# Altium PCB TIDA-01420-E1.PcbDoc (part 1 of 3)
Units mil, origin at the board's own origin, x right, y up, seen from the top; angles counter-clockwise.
Board outline 6575 x 7007.88 mil, 4 copper layers (Top Layer, GND, PWR, Bottom Layer), stack 79.834 mil thick; 326 components, 128 nets, 736 pads, 186 vias.
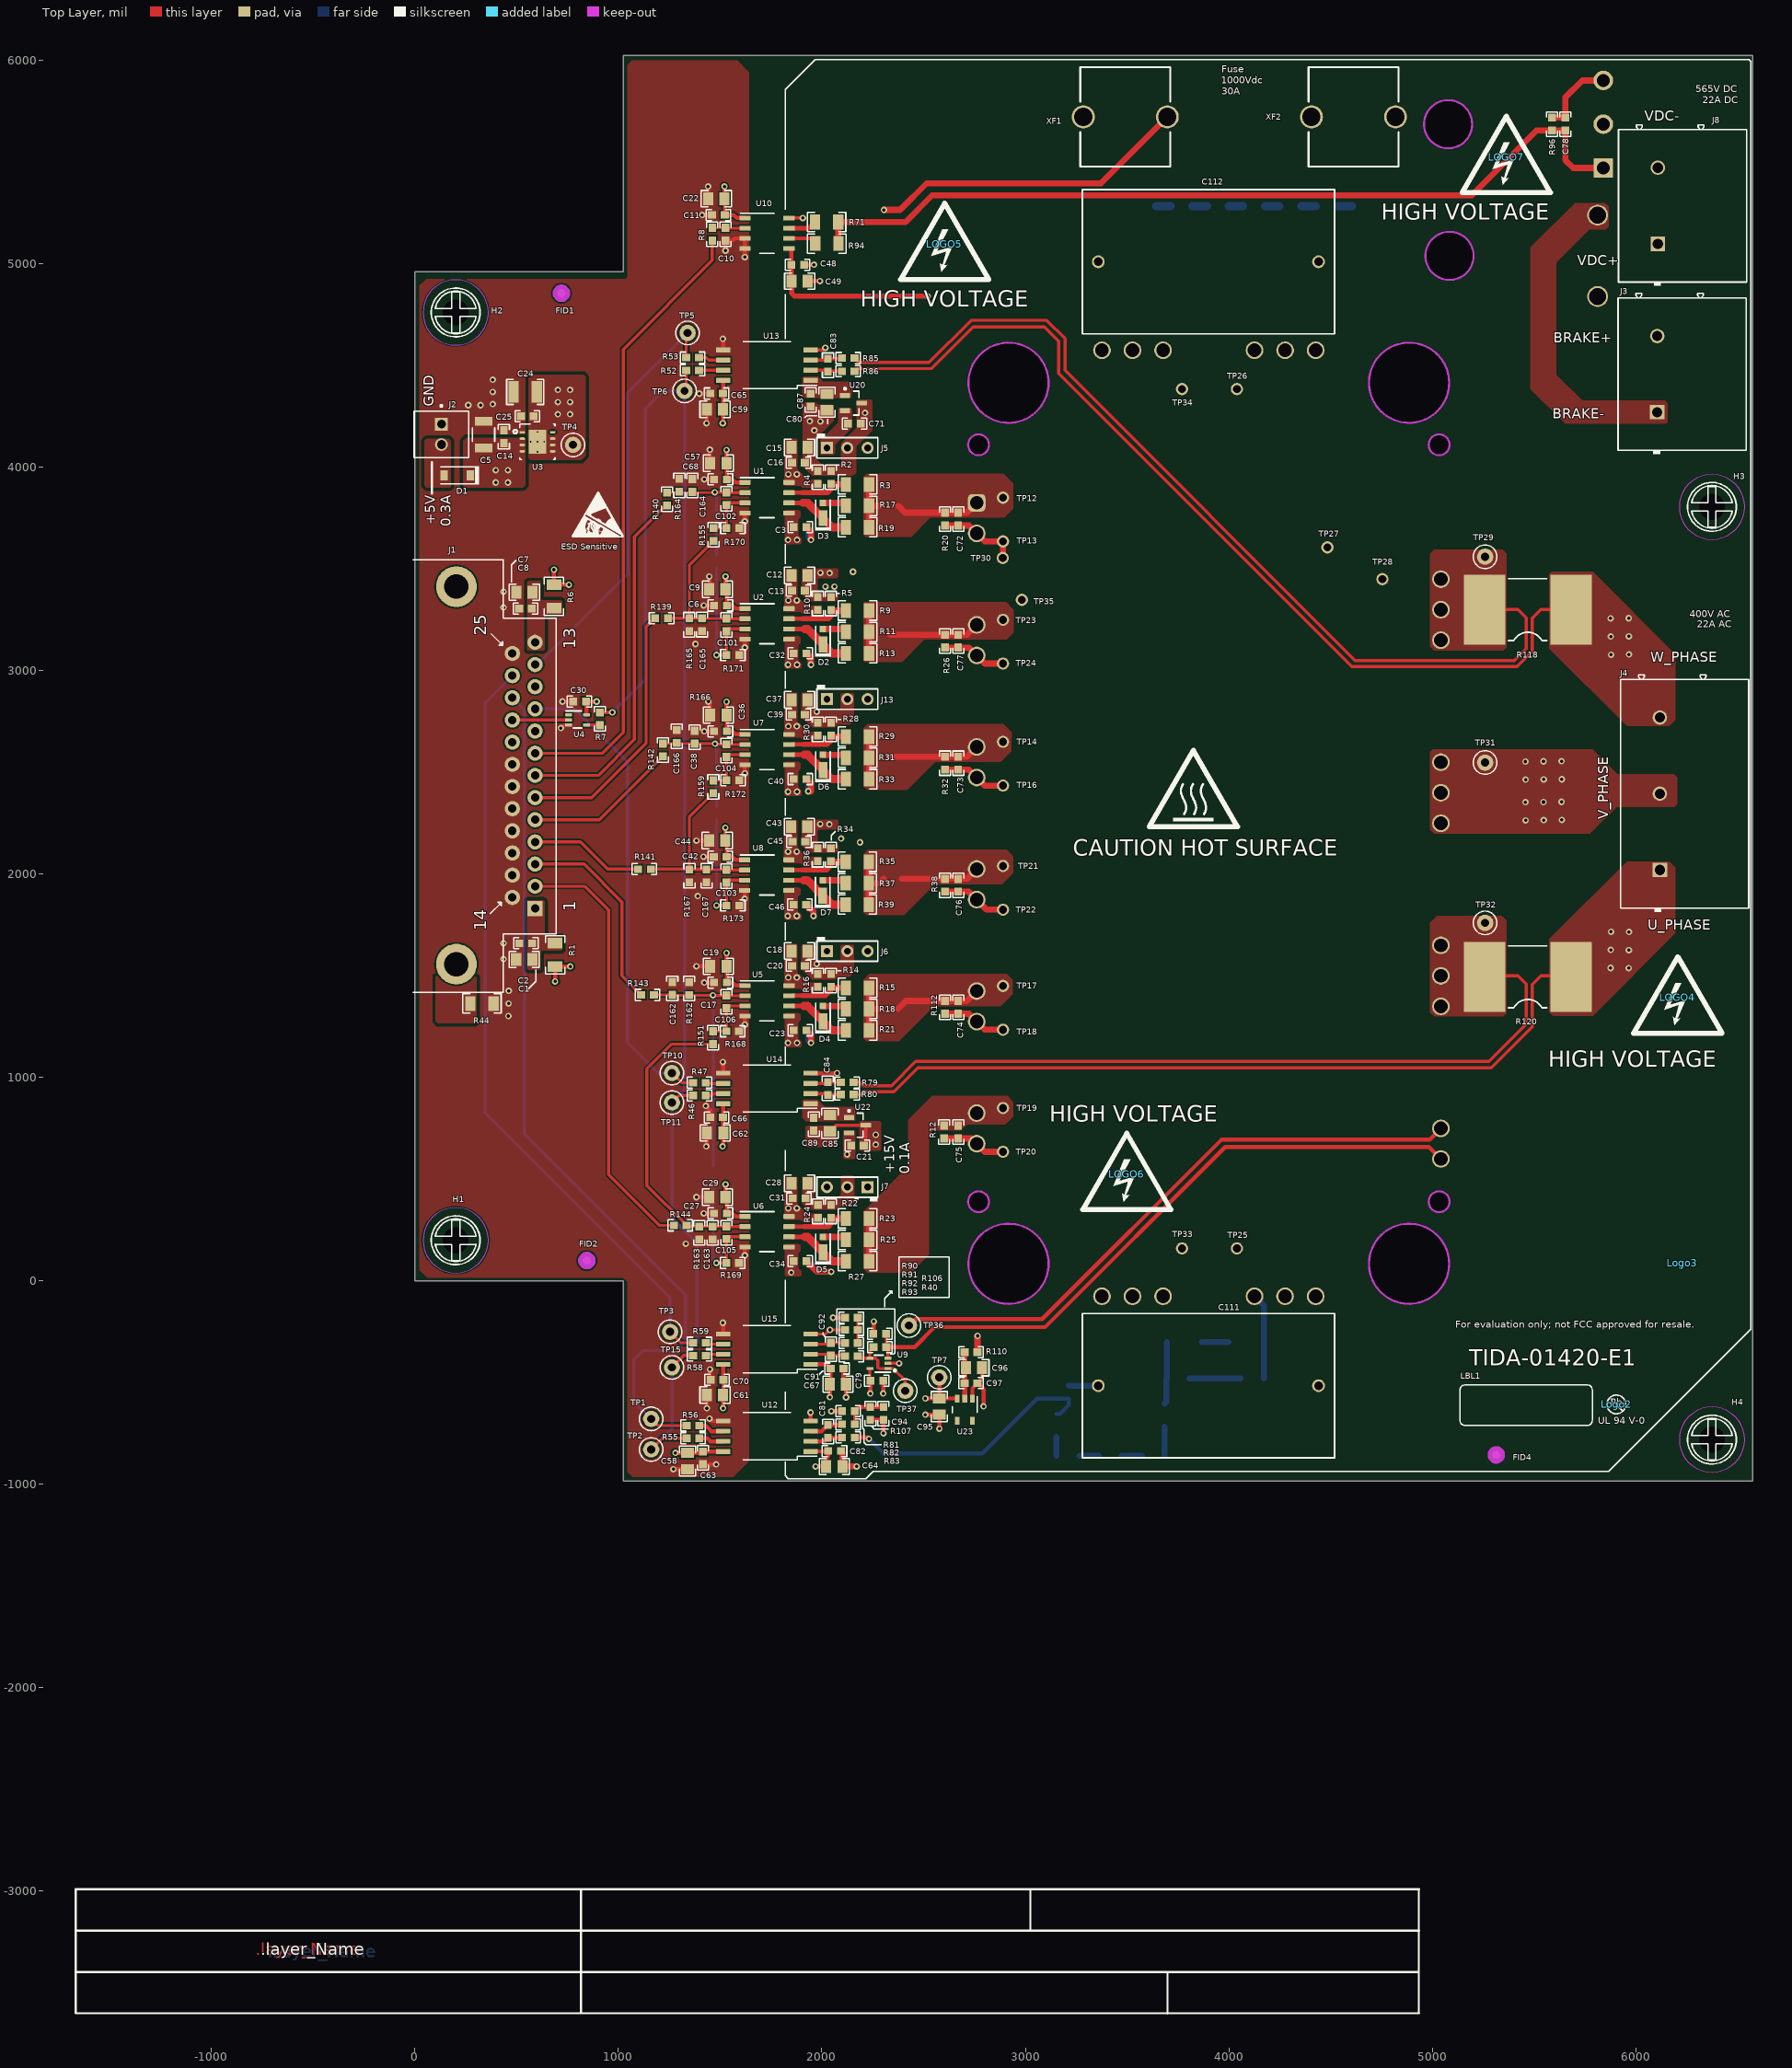
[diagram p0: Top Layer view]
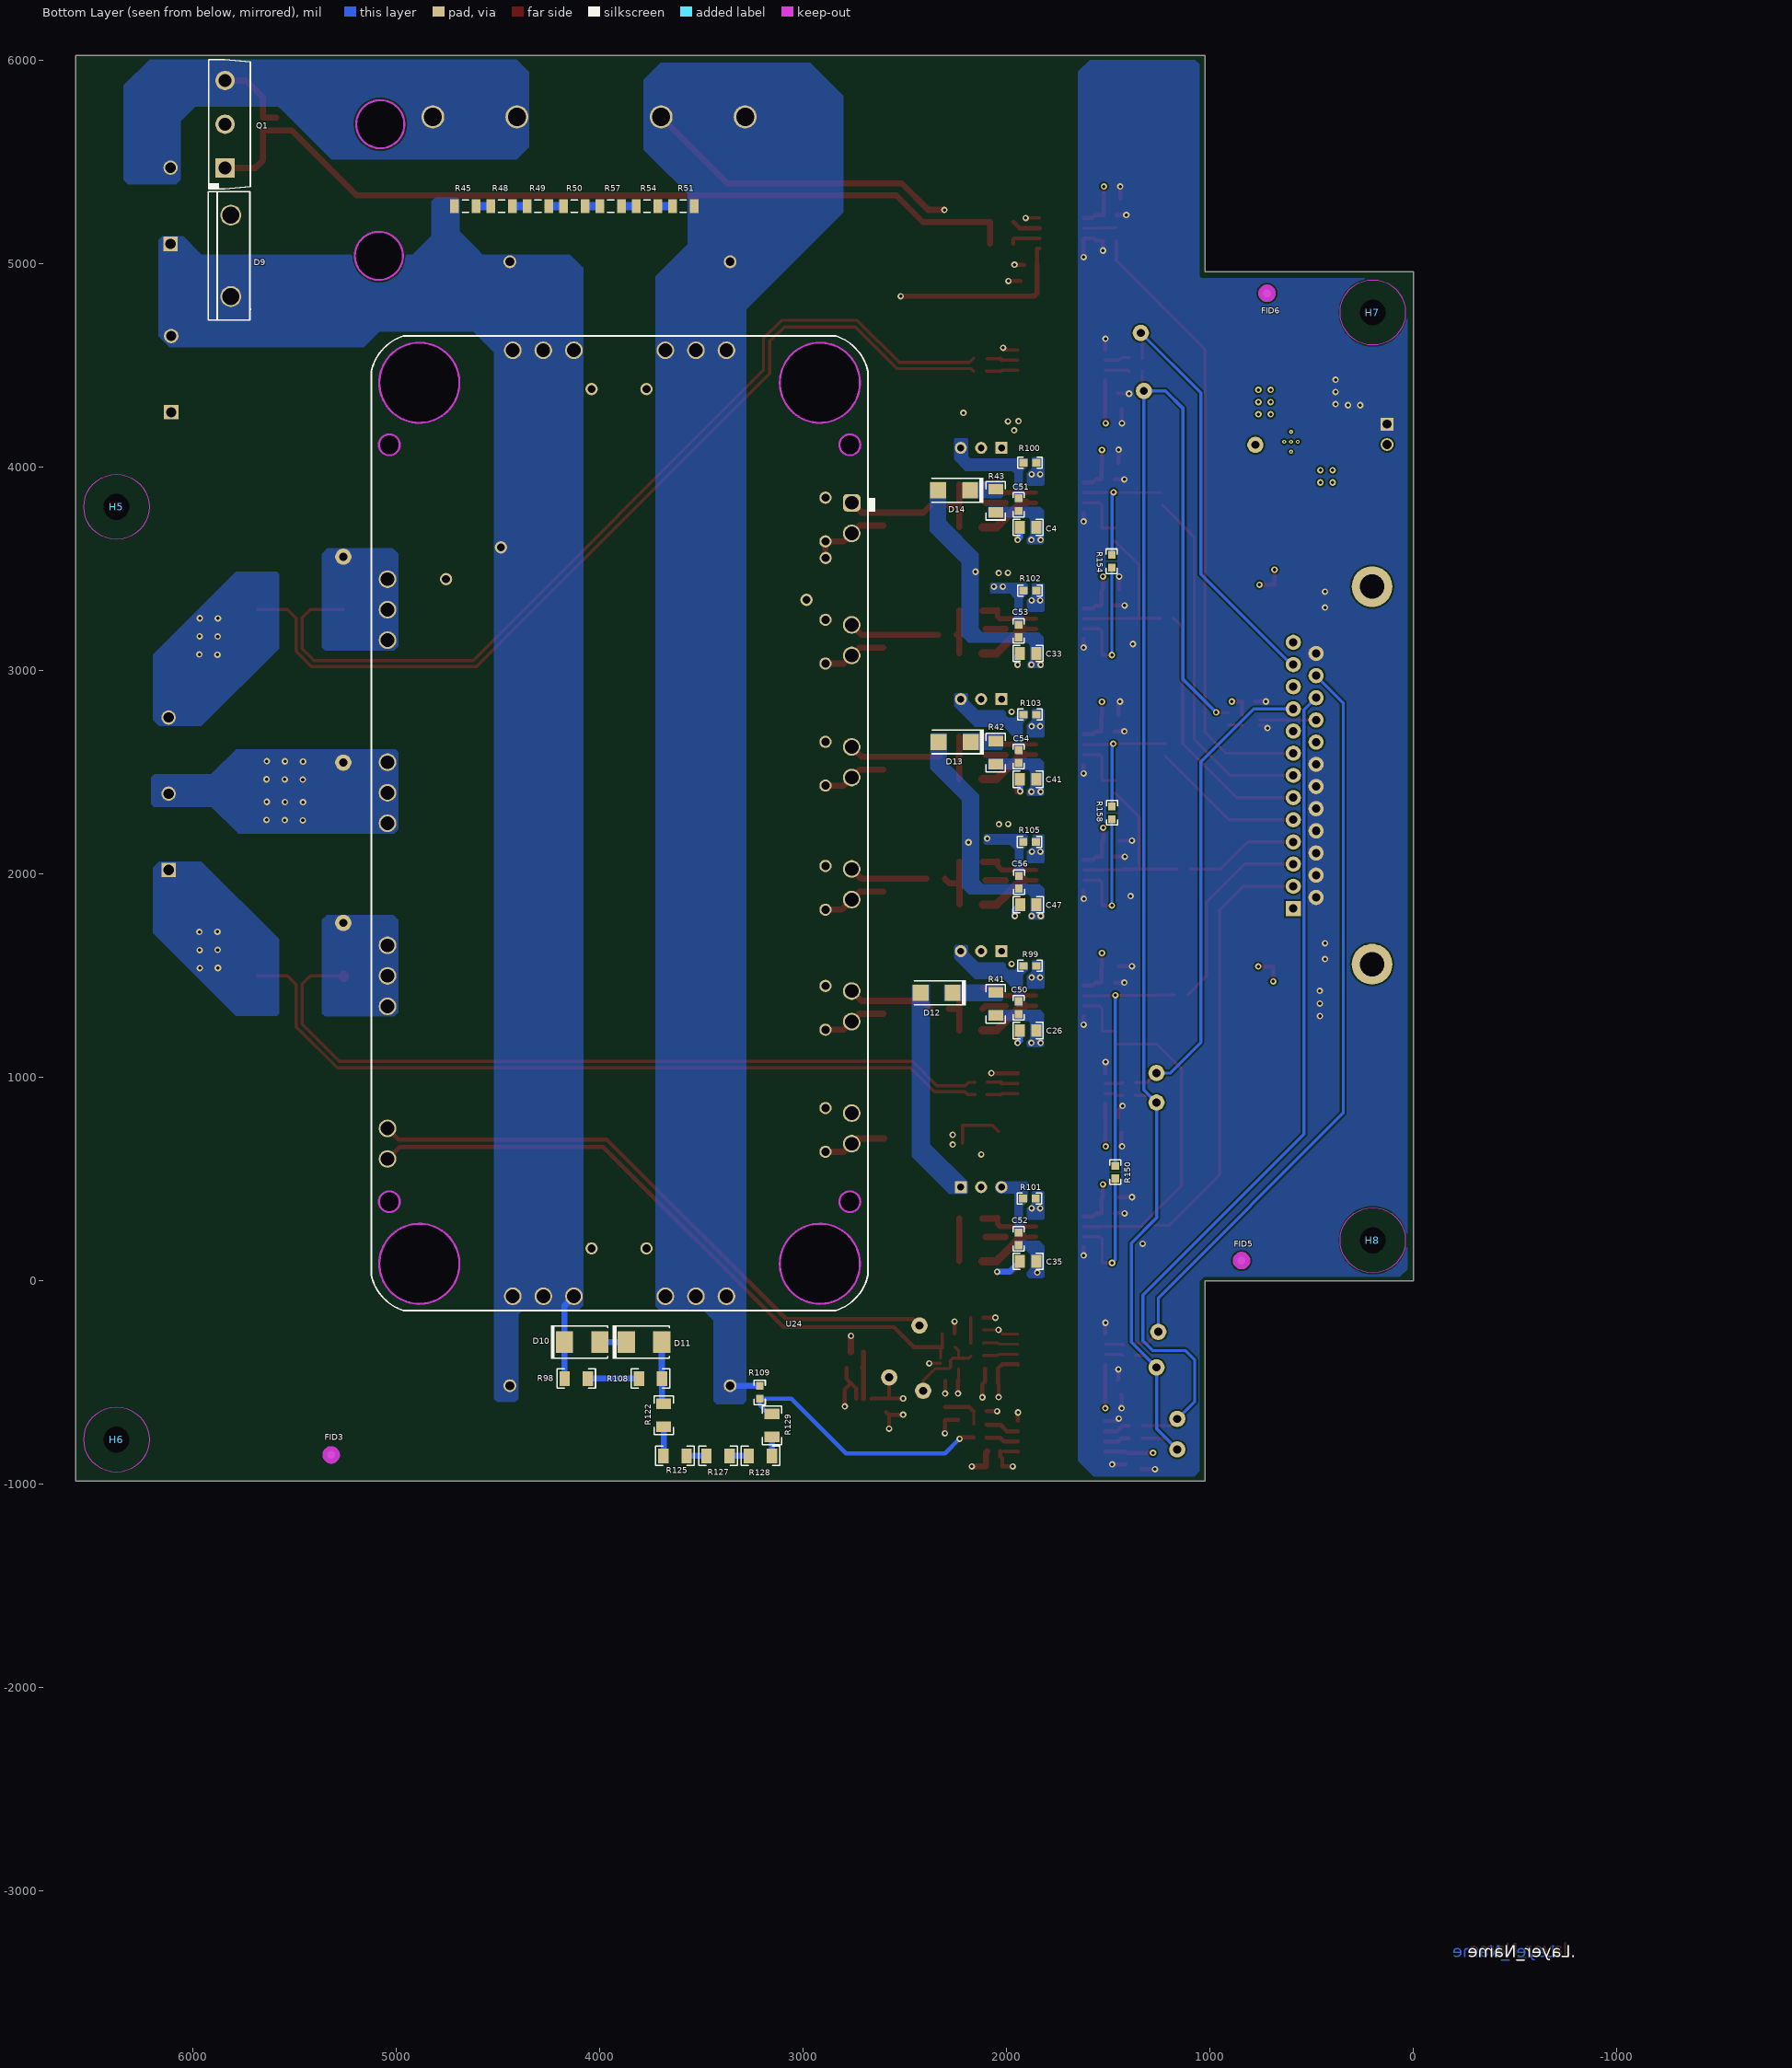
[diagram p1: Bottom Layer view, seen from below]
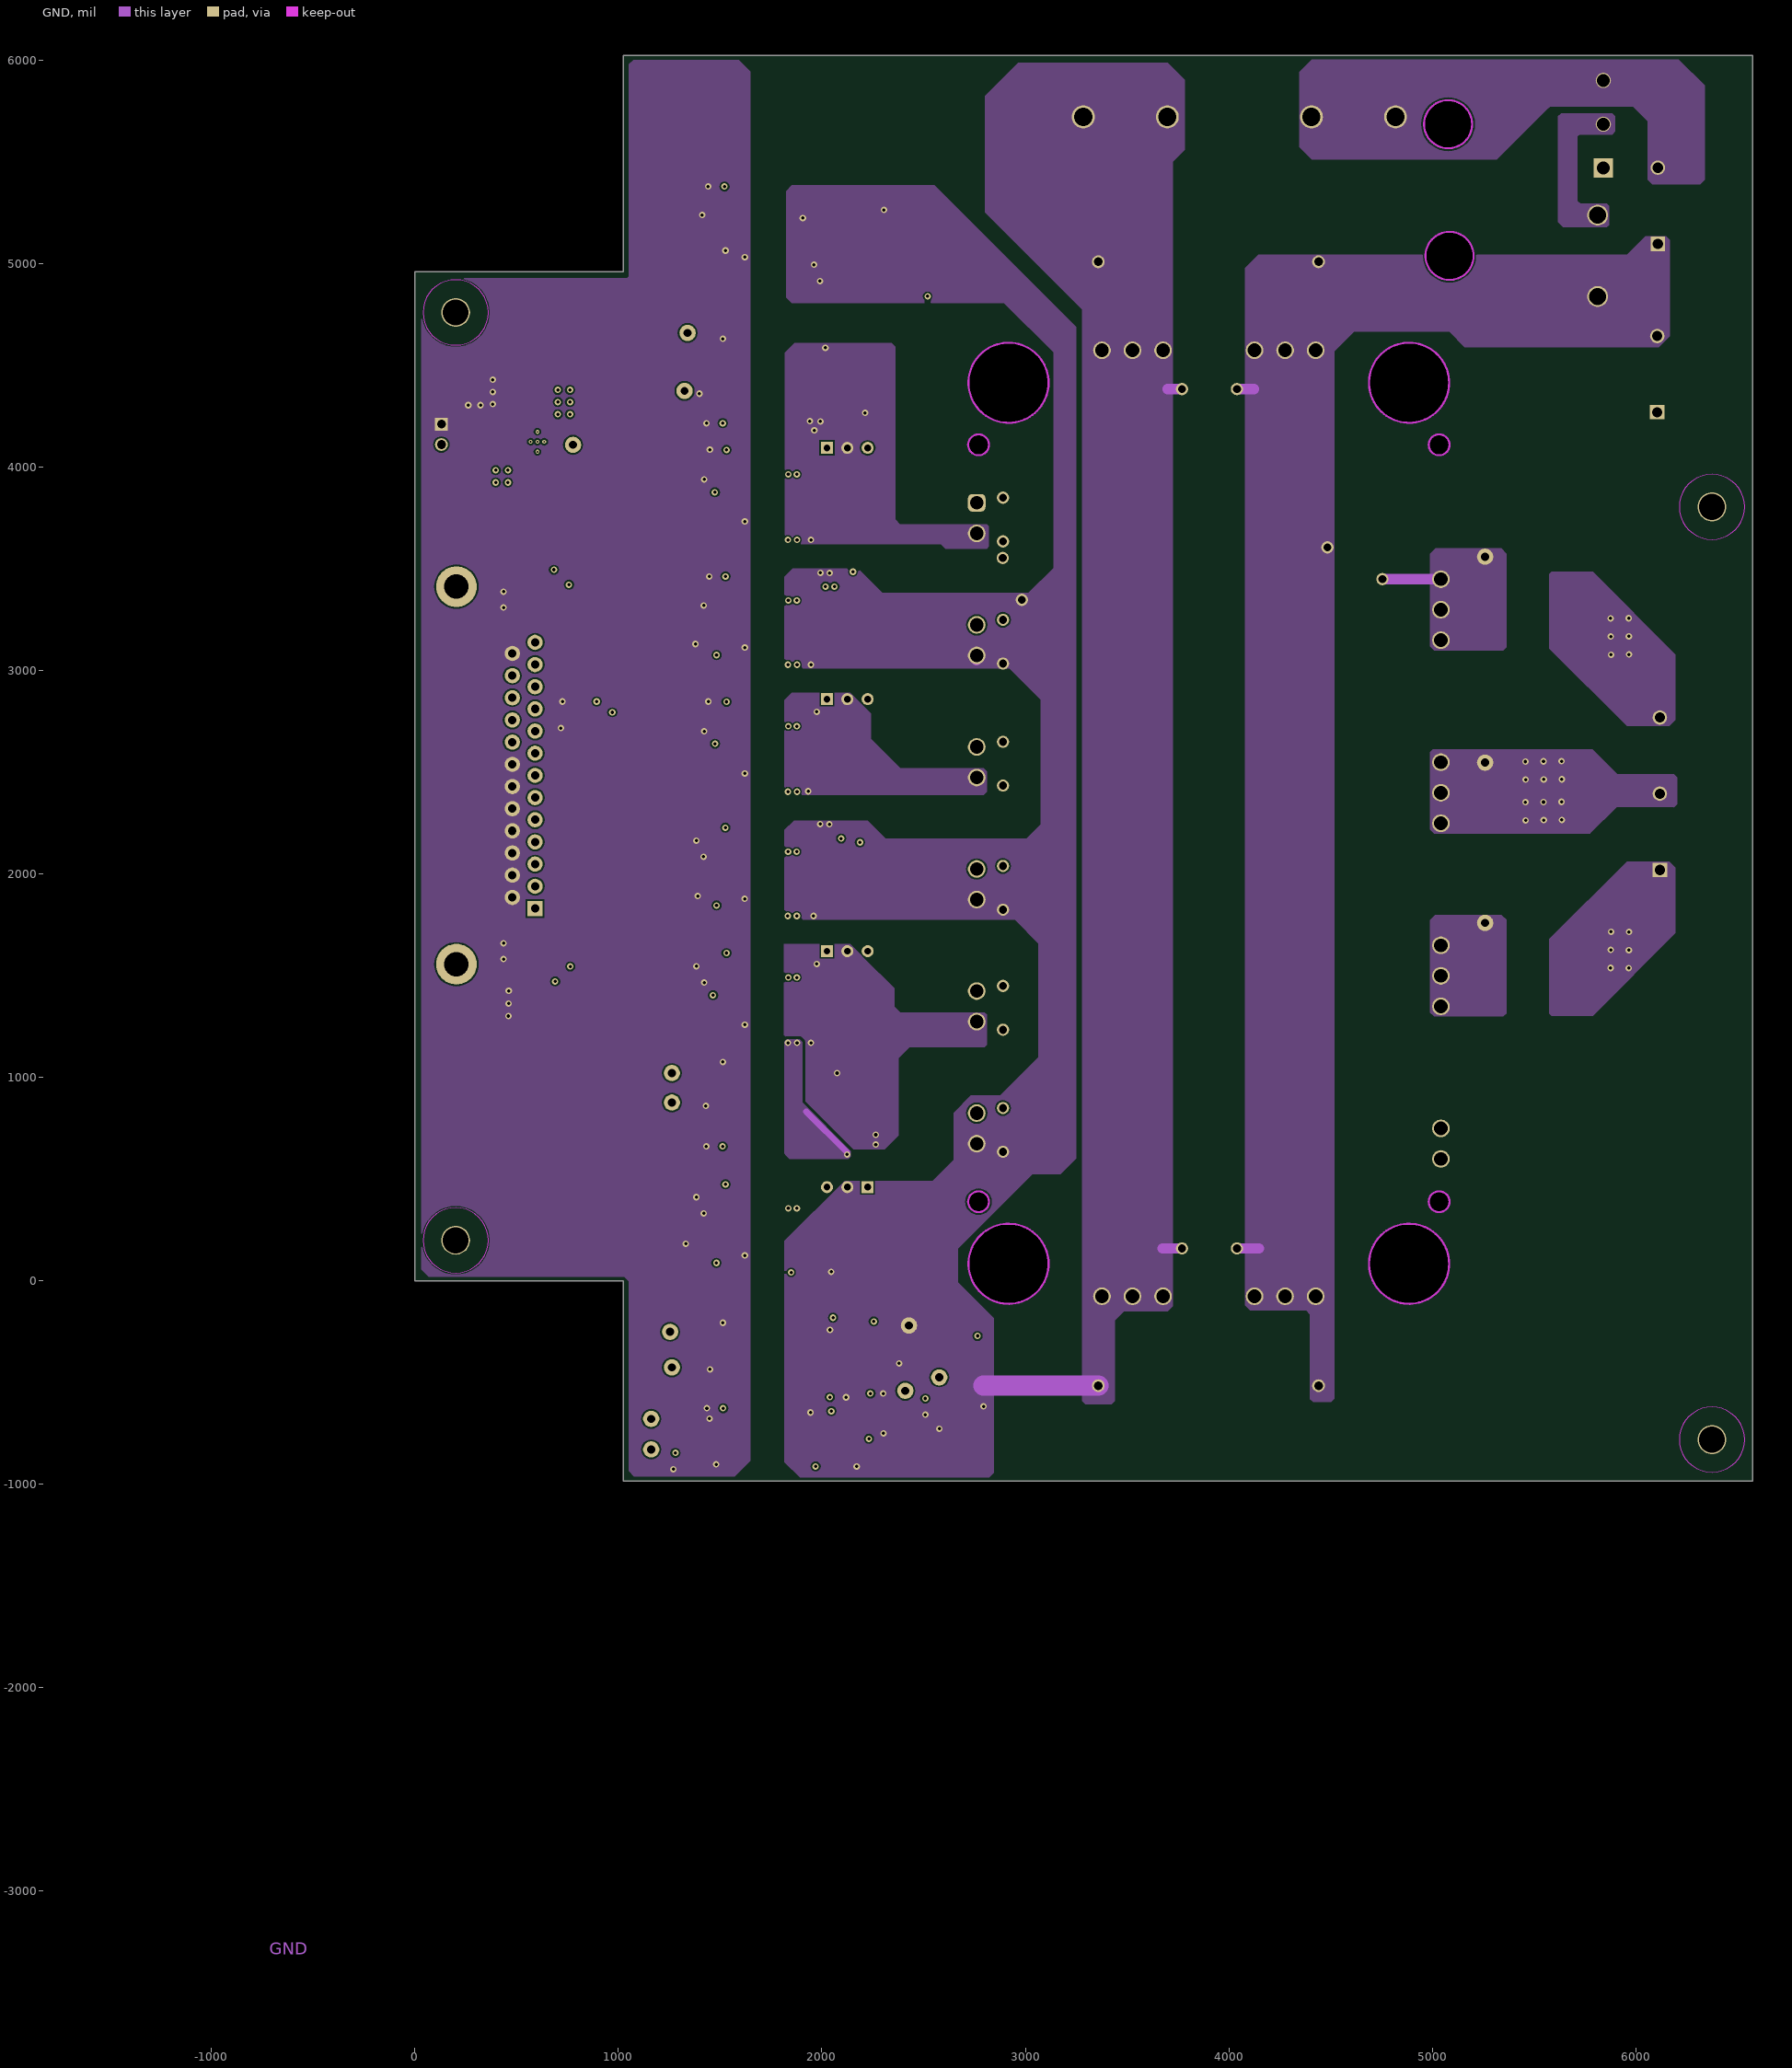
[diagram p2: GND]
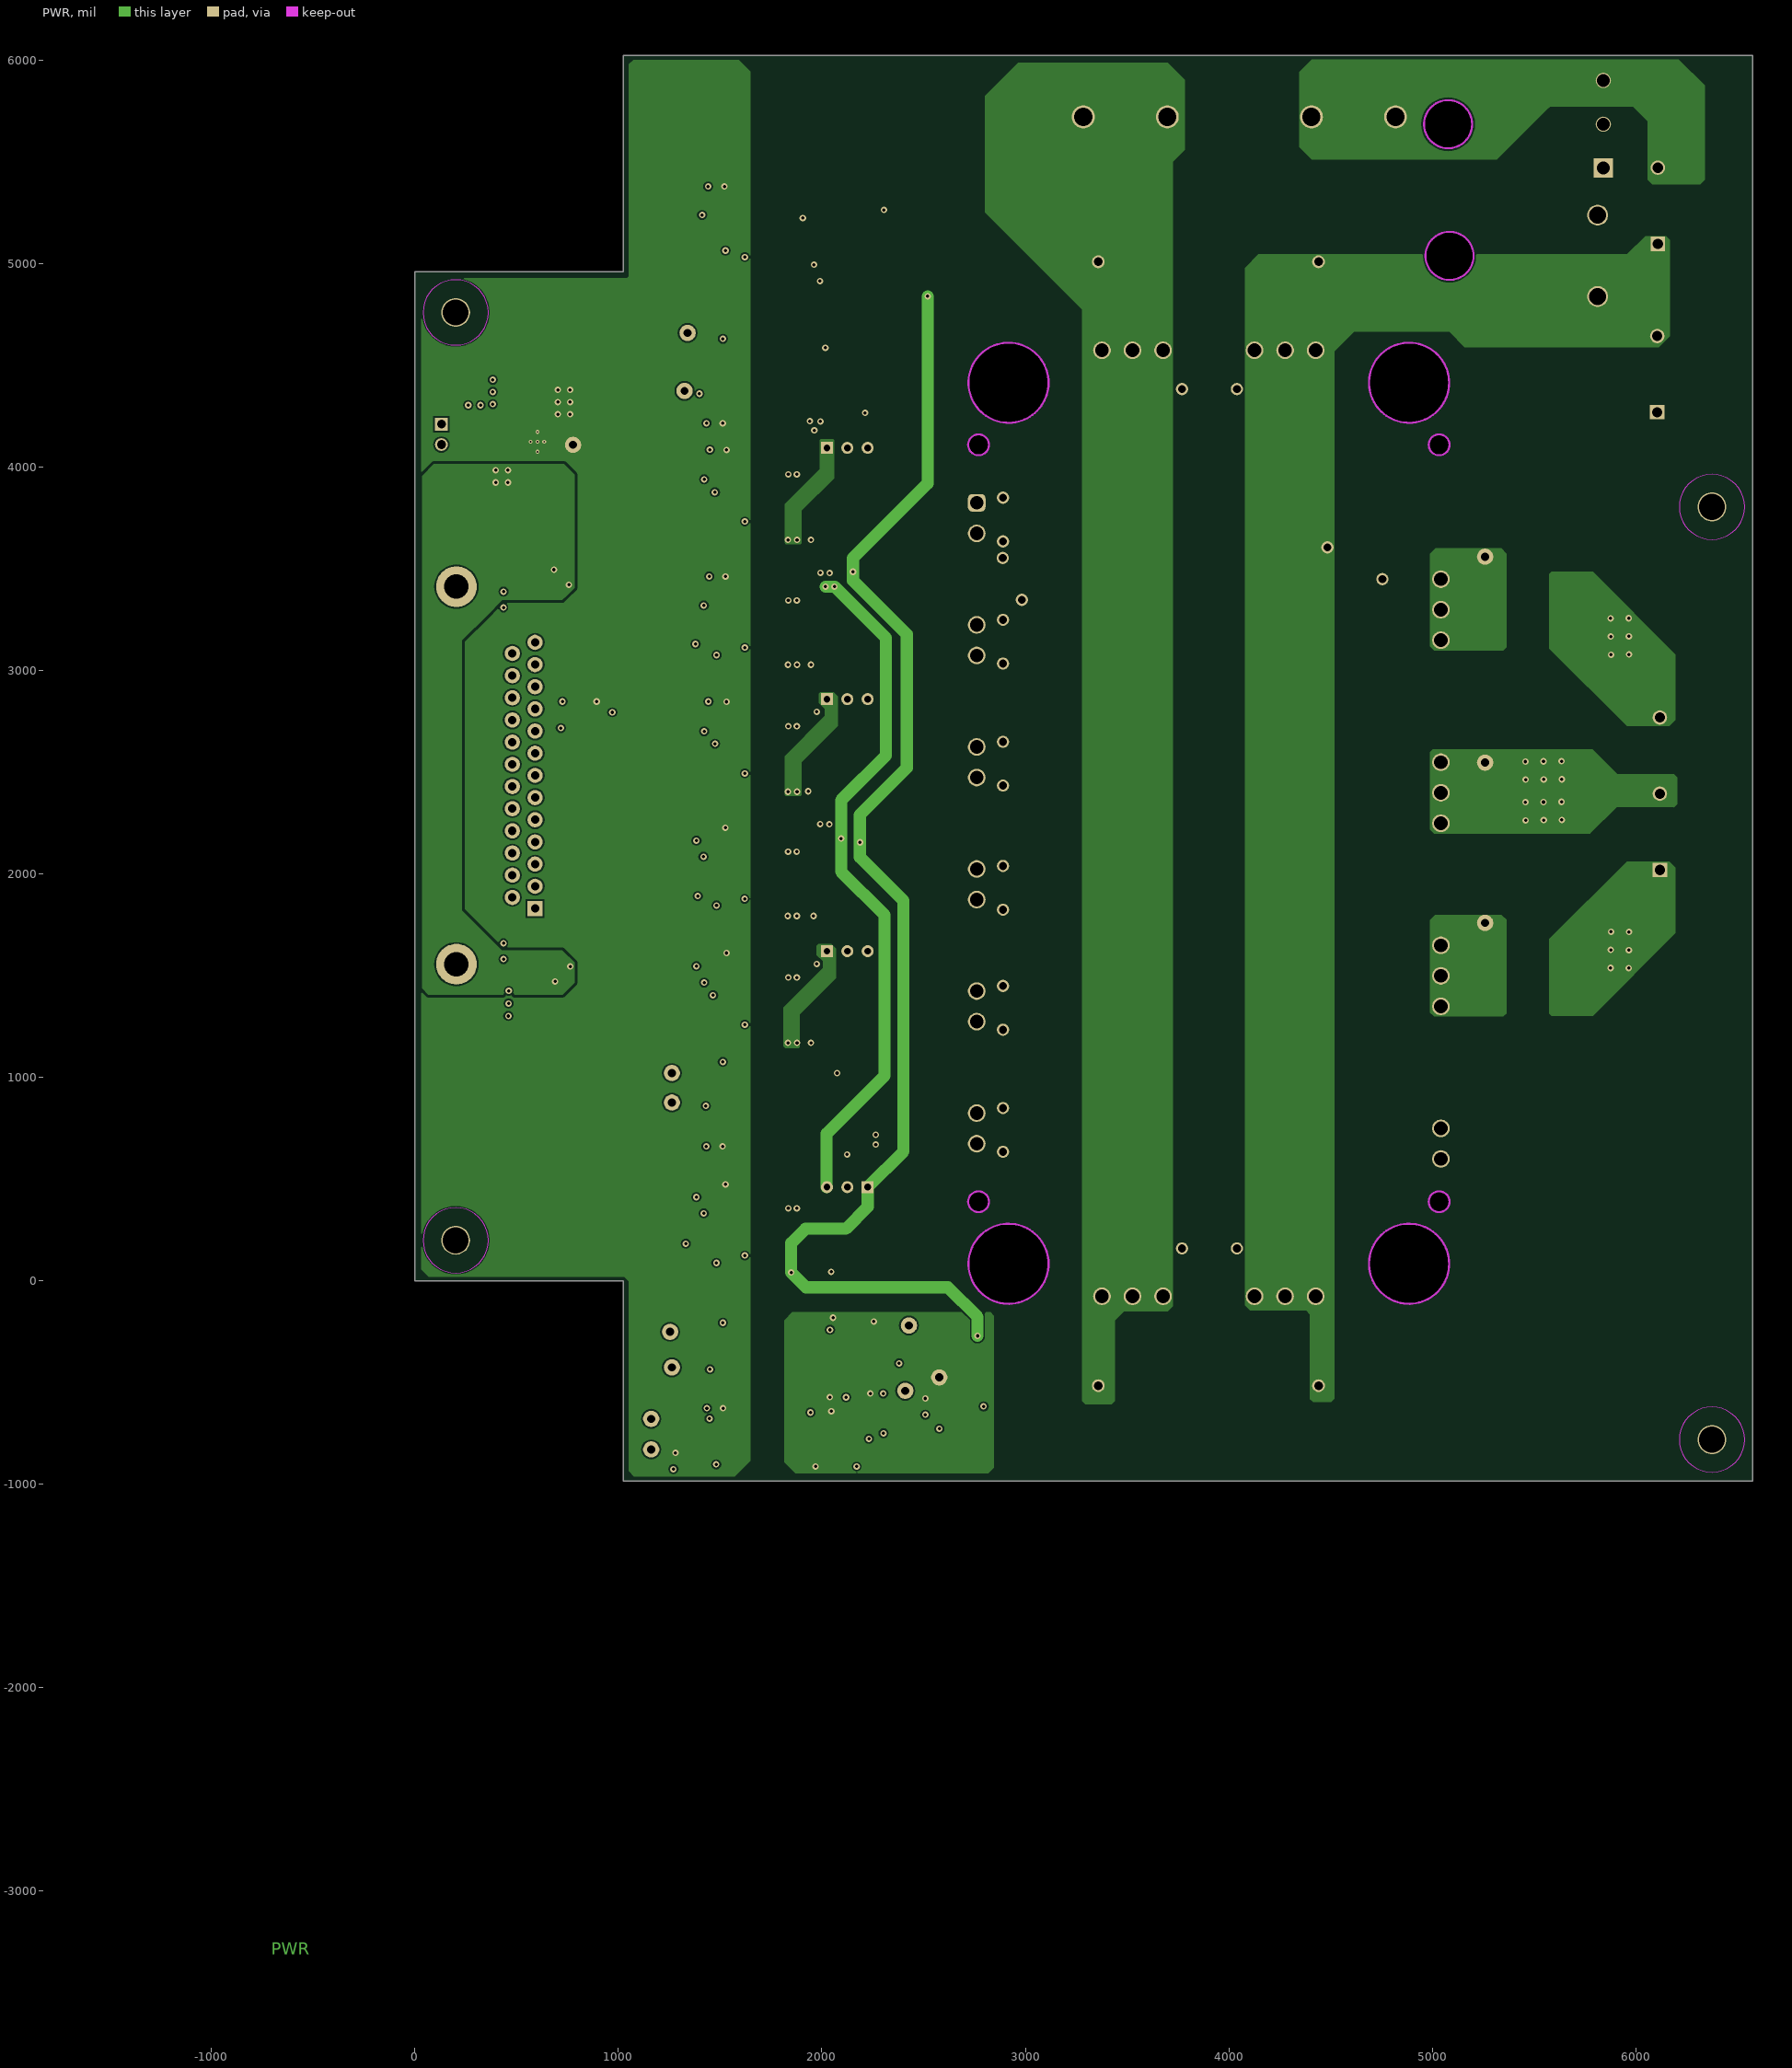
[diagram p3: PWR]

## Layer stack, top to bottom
Top Solder: solder mask 0.4, Solder Resist, Dk 3.5
Top Layer: signal copper 1.4
Dielectric1: core 59.2, FR-4, Dk 4.8
GND: signal copper 1.417
Dielectric 2: prepreg 5, Dk 4.2
PWR: signal copper 1.417
Dielectric 3: core 10, Dk 4.2
Bottom Layer: signal copper 1.4
Bottom Solder: solder mask 0.4, Solder Resist, Dk 3.5

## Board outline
0,0 0,4960.63 1024.73,4960.63 1024.73,6023.62 6575,6023.62 6575,-984.25 1024.73,-984.25 1024.73,0

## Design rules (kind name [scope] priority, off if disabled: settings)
AcuteAngle [All] p1: minimum=4.50000000000000E+0001 checktracksonly=FALSE
AssemblyTestPointUsage [All] p1: valid=2
Clearance "High voltage" [InNetClass('HIGH voltage') vs InNetClass('LOW voltage')] p1: gap=8 except(120: Track-Track Track-Via Track-Poly)
Clearance Clearance_1 [All] p2: gap=8 except(15: Poly-Poly)
Clearance Clearance_Wtop [InNet('W_PHASE_REF') vs InNet('W_PHASE')] p3: gap=0 except(15: Track-Track)
Clearance Clearance_Vtop [InNet('VDC-') vs InNet('NetR40_1')] p4: gap=0 except(8: Track-Track)
Clearance Clearance_utop [InNet('U_PHASE_REF') vs InNet('U_PHASE')] p5: gap=0 except(15: Track-Track)
Clearance Clearance_MTG_COPPER [InPadClass('MTG') vs InPolygon] p6: gap=40
Clearance Clearance_Boardedge_poly [OnCopper and InPolygon vs IsKeepOut] p7: gap=20
Clearance "Shape to Shape" [InPolygon vs InPolygon] p8: gap=20
Clearance "shape to all" [InPolygon] p9: gap=15
Clearance "Clearance_via_thr pin" [IsVia vs IsThruPin] p10: gap=8
Clearance "SMD to Via" [IsSMTPin vs IsVia] p11: gap=8
DiffPairsRouting DiffPair_DiffPairsRouting [InDifferentialPair ('kan')] p1: maxlimit=10 minlimit=10 mostfreqgap=10 toplayer_minwidth=15 toplayer_maxwidth=15 toplayer_prefwidth=15 midlayer1_minwidth=15 midlayer1_maxwidth=15 midlayer1_prefwidth=15 midlayer2_minwidth=15 midlayer2_maxwidth=15 midlayer2_prefwidth=15 bottomlayer_minwidth=15 bottomlayer_maxwidth=15 bottomlayer_prefwidth=15 maxuncoupledlength=500
DiffPairsRouting DiffPair_DiffPairsRouting_1 [InDifferentialPair ('kan')] p2: maxlimit=10 minlimit=10 mostfreqgap=10 toplayer_minwidth=15 toplayer_maxwidth=15 toplayer_prefwidth=15 midlayer1_minwidth=15 midlayer1_maxwidth=15 midlayer1_prefwidth=15 midlayer2_minwidth=15 midlayer2_maxwidth=15 midlayer2_prefwidth=15 bottomlayer_minwidth=15 bottomlayer_maxwidth=15 bottomlayer_prefwidth=15 maxuncoupledlength=500
DiffPairsRouting [All] p3: maxlimit=100 minlimit=10 mostfreqgap=10 toplayer_minwidth=15 toplayer_maxwidth=15 toplayer_prefwidth=15 midlayer1_minwidth=15 midlayer1_maxwidth=15 midlayer1_prefwidth=15 midlayer2_minwidth=15 midlayer2_maxwidth=15 midlayer2_prefwidth=15 bottomlayer_minwidth=15 bottomlayer_maxwidth=15 bottomlayer_prefwidth=15 maxuncoupledlength=1000
FabricationTestPointUsage TestPointUsage [All] p1: valid=2 allowmultiple=FALSE
FabricationTestpoint Testpoint [All] p1: side=3 testpointundercomponent=TRUE minsize=40 maxsize=100 preferedsize=60 minholesize=0 maxholesize=40 preferedholesize=32 testpointgrid=1 allowsidetop=TRUE allowsidebottom=TRUE usegrid=TRUE gridtolerance=0.01
FanoutControl Fanout_LCC [IsLCC] p1: bgadir=Out bgaviamode=Centered fanoutstyle=Auto fanoutdirection=Alternating viagrid=1 // Fanout_LCC (Default Rule)
FanoutControl Fanout_BGA [IsBGA] p2: bgadir=Out bgaviamode=Centered fanoutstyle=Auto fanoutdirection=Alternating viagrid=1 // Fanout_BGA (Default Rule)
FanoutControl Fanout_Default [All] p4: bgadir=Out bgaviamode=Centered fanoutstyle=Auto fanoutdirection=Alternating viagrid=1 // Fanout_Default (Default Rule)
FanoutControl Fanout_Small [(CompPinCount < 5)] p5: bgadir=Out bgaviamode=Centered fanoutstyle=Auto fanoutdirection=OutThenIn viagrid=1 // Fanout_Small (Default Rule)
HoleSize [All] p1: absolutevalues=TRUE maxlimit=1500 minlimit=7 maxpercent=80.000 minpercent=20.000
MatchedLengths DiffPair_MatchedLengths [InDifferentialPair ('kan')] p1: tolerance=1000 checknetsindiffpair=TRUE checkdiffpairvsdiffpair=FALSE checkxsignals=FALSE checkothers=FALSE
MatchedLengths DiffPair_MatchedLengths_1 [InDifferentialPair ('kan')] p2: tolerance=1000 checknetsindiffpair=TRUE checkdiffpairvsdiffpair=FALSE checkxsignals=FALSE checkothers=FALSE
MinimumAnnularRing [All] p1: minimumring=5
MinimumAnnularRing MinimumAnnularRing_ThermalPadVias [IsVia and InAnyComponent] p2: minimumring=5.91
MinimumSolderMaskSliver MinimumSolderMaskSliver_Logo [InComponentClass('Logo') vs InComponentClass('Logo')] p1: minsoldermaskwidth=0.7
MinimumSolderMaskSliver [All] p2: minsoldermaskwidth=3.94
PlaneClearance [All] p1: clearance=15
PlaneConnect [All] p1: planeconnectstyle=Direct reliefexpansion=10 reliefentries=4 reliefconductorwidth=10 reliefairgap=10
PolygonConnect [All] p1: connectstyle=Direct reliefconductorwidth=10 reliefentries=4 polygonreliefangle="90 Angle" airgapwidth=10
RoutingVias RoutingVias_power [InNetClass('POWER')] p1: holewidth=16 width=32 viastyle="Through Hole" minholewidth=7.87 minwidth=19.68 maxholewidth=16 maxwidth=32
RoutingVias ThermalPadVias [IsVia and InAnyComponent] p2: holewidth=8 width=20 viastyle="Through Hole" minholewidth=7.87 minwidth=19 maxholewidth=12 maxwidth=24
RoutingVias [All] p3: holewidth=12 width=24 viastyle="Through Hole" minholewidth=12 minwidth=24 maxholewidth=16 maxwidth=32
SMDToCorner [All] p1: distance=30000
SilkToSilkClearance [All] p1: silktosilkclearance=5
SilkToSolderMaskClearance SilkscreenOverComponentPads [IsPad] p1: minsilkscreentomaskgap=5 clearancetoexposedcopper=TRUE
SolderMaskExpansion [All] p1: expansion=3
Width Width_power [InNetClass('pwr')] p1: maxlimit=200 minlimit=8 preferedwidth=20
Width [All] p2: maxlimit=250 minlimit=10 preferedwidth=20 checkconnectedcopper=TRUE
16 further rules are at their usual default settings.

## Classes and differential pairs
component class "TIDA-01420-E1_Gate drivers": C3 C4 C6 C9 C10 C11 C12 C13 C15 C16 C17 C18 C19 C20 C22 C23 C26 C27 C28 C29 C31 C32 C33 C34 C35 C36 C37 C38 C39 C40 C41 C42 C43 C44 C45 C46 C47 C48 C49 C50 C51 C52 C53 C54 C56 C57 C68 C101 C102 C103 C104 C105 C106 C162 C163 C164 C165 C166 C167 D2 D3 D4 D5 D6 D7 D12 D13 D14 J5 J6 J7 J13 R2 R3 R4 R5 R8 R9 R10 R11 R13 R14 R15 R16 R17 R18 R19 R21 R22 R23 R24 R25 R27 R28 R29 R30 R31 R33 R34 R35 R36 R37 R39 R41 R42 R43 R71 R94 R99 R100 R101 R102 R103 R105 R139 R140 R141 R142 R143 R144 R150 R151 R154 R155 R158 R159 R162 R163 R164 R165 R166 R167 R168 R169 R170 R171 R172 R173 U1 U2 U5 U6 U7 U8 U10
component class "TIDA-01420-E1_IGBT Module, Temp and DC link sense": C58 C61 C63 C64 C67 C70 C72 C73 C74 C75 C76 C77 C78 C79 C81 C82 C91 C92 C94 C95 C96 C97 C111 C112 D9 D10 D11 J3 J4 J8 Q1 R12 R20 R26 R32 R38 R40 R45 R48 R49 R50 R51 R54 R55 R56 R57 R58 R59 R81 R82 R83 R90 R91 R92 R93 R96 R98 R106 R107 R108 R109 R110 R112 R118 R120 R122 R125 R127 R128 R129 TP1 TP2 TP3 TP7 TP12 TP13 TP14 TP15 TP16 TP17 TP18 TP19 TP20 TP21 TP22 TP23 TP24 TP25 TP26 TP27 TP28 TP29 TP30 TP31 TP32 TP33 TP34 TP35 TP36 TP37 U9 U12 U15 U23 U24 XF1 XF2
component class "TIDA-01420-E1_Current sense, MCU Interface": C1 C2 C5 C7 C8 C14 C21 C24 C25 C30 C59 C62 C65 C66 C71 C80 C83 C84 C85 C87 C89 D1 J1 J2 R1 R6 R7 R44 R46 R47 R52 R53 R79 R80 R85 R86 TP4 TP5 TP6 TP10 TP11 U3 U4 U13 U14 U20 U22
component class TIDA-01420-E1_EVM_Hardware: "CAUTION HOT SURFACE" "ESD Sensitive" FID1 FID2 FID3 FID4 FID5 FID6 H1 H2 H3 H4 H5 H6 H7 H8 LBL1 Logo2 Logo3 LOGO4 LOGO5 LOGO6 LOGO7 ZZ1 ZZ2 ZZ3 ZZ4
component class FiducialMark: FID1 FID2 FID3 FID4 FID5 FID6
pad class MTG: H1-1 H2-1 H3-1 H4-1 H5-0 H6-0 H7-0 H8-0
component class Header: J5 J6 J7 J13
component class AssemblyNote: ZZ1 ZZ2 ZZ3 ZZ4
component class Label: LBL1

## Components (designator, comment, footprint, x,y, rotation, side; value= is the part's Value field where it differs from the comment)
C1 "C2012X7R1V475K125AC" 0805_HV 537,1580 r0 top
C2 "C1608X7R1H104K" 0603 545,1660 r0 top
C3 "C1608X7R1H474K080AC" 0603 1893,3705 r0 top
C4 "C2012X7R1V475K125AC" 0805_HV 1894,3704 r0 bottom
C5 "UMK325AB7106KM-T" 1210_280 337,4160 r90 top
C6 "C1608X7R1H104K" 0603 1501.3,3320 r180 top
C7 "C2012X7R1V475K125AC" 0805_HV 538,3385 r180 top
C8 "C1608X7R1H104K" 0603 543,3305 r180 top
C9 "C2012X7R1V475K125AC" 0805_HV 1486.3,3400 r180 top
C10 "GRM1885C1H120JA01D" 0603 1526.3,5145 r270 top
C11 "C1608X7R1H104K" 0603 1491.3,5240 r180 top
C12 "C2012X7R1V475K125AC" 0805_HV 1890,3468 r180 top
C13 "C1608X7R1H474K080AC" 0603 1885,3393 r180 top
C14 "C1608X7R1H104K" 0603 437,4150 r90 top
C15 "C2012X7R1V475K125AC" 0805_HV 1890,4097 r180 top
C16 "C1608X7R1H474K080AC" 0603 1885,4022 r180 top
C17 "C1608X7R1H104K" 0603 1501.3,1466.97 r180 top
C18 "C2012X7R1V475K125AC" 0805_HV 1890,1621.97 r180 top
C19 "C2012X7R1V475K125AC" 0805_HV 1491.3,1546.97 r180 top
C20 "C1608X7R1H474K080AC" 0603 1885,1548.97 r180 top
C21 "C1608X7R1H104K" 0603 2174.77,665.55 r180 top
C22 "C2012X7R1V475K125AC" 0805_HV 1481.3,5320 r180 top
C23 "C1608X7R1H474K080AC" 0603 1893,1231.97 r0 top
C24 "C1210C107M4PAC7800" 1210_270 542,4370 r180 top
C25 "C1608X7R1H104K" 0603 552,4250 r180 top
C26 "C2012X7R1V475K125AC" 0805_HV 1894,1230.97 r0 bottom
C27 "C1608X7R1H104K" 0603 1501.3,332 r180 top
C28 "C2012X7R1V475K125AC" 0805_HV 1890,480 r180 top
C29 "C2012X7R1V475K125AC" 0805_HV 1486.3,412 r180 top
C30 "C1608X7R1H104K" 0603 809,2848 r180 top
C31 "C1608X7R1H474K080AC" 0603 1888,406 r180 top
C32 "C1608X7R1H474K080AC" 0603 1893,3085 r0 top
C33 "C2012X7R1V475K125AC" 0805_HV 1894,3085 r0 bottom
C34 "C1608X7R1H474K080AC" 0603 1893,97 r0 top
C35 "C2012X7R1V475K125AC" 0805_HV 1894,97 r0 bottom
C36 "C1608X7R1H104K" 0603 1501.3,2701.97 r180 top
C37 "C2012X7R1V475K125AC" 0805_HV 1890,2856.97 r180 top
C38 "C2012X7R1V475K125AC" 0805_HV 1491.3,2781.97 r180 top
C39 "C1608X7R1H474K080AC" 0603 1885,2783.97 r180 top
C40 "C1608X7R1H474K080AC" 0603 1893,2466.97 r0 top
C41 "C2012X7R1V475K125AC" 0805_HV 1894,2465.97 r0 bottom
C42 "C1608X7R1H104K" 0603 1500.3,2085 r180 top
C43 "C2012X7R1V475K125AC" 0805_HV 1889,2233 r180 top
C44 "C2012X7R1V475K125AC" 0805_HV 1485.3,2165 r180 top
C45 "C1608X7R1H474K080AC" 0603 1887,2159 r180 top
C46 "C1608X7R1H474K080AC" 0603 1892,1850 r0 top
C47 "C2012X7R1V475K125AC" 0805_HV 1893,1850 r0 bottom
C48 "C1608X7R1H474K080AC" 0603 1881,4995 r0 top
C49 "C2012X7R1V475K125AC" 0805_HV 1891,4915 r0 top
C50 "C1608X7R1H474K080AC" 0603 1940,1342.97 r90 bottom
C51 "C1608X7R1H474K080AC" 0603 1940,3816 r90 bottom
C52 "C1608X7R1H474K080AC" 0603 1940,207 r90 bottom
C53 "C1608X7R1H474K080AC" 0603 1940,3195 r90 bottom
C54 "C1608X7R1H474K080AC" 0603 1940,2577.97 r90 bottom
C56 "C1608X7R1H474K080AC" 0603 1939,1960 r90 bottom
C57 "C2012X7R1V475K125AC" 0805_HV 1491.3,4020 r180 top
C58 "C2012X7R1V475K125AC" 0805_HV 1340,-885 r90 top
C59 "C2012X7R1V475K125AC" 0805_HV 1474.73,4284.45 r0 top
C61 "C2012X7R1V475K125AC" 0805_HV 1474.73,-560.55 r0 top
C62 "C2012X7R1V475K125AC" 0805_HV 1475.5,728 r0 top
C63 "C1608X7R1H104K" 0603 1415,-870 r90 top
C64 "C2012X7R1V475K125AC" 0805_HV 2061,-912 r180 top
C65 "C1608X7R1H104K" 0603 1482.73,4362.45 r0 top
C66 "C1608X7R1H104K" 0603 1482.5,804 r0 top
C67 "C2012X7R1V475K125AC" 0805_HV 2079,-508 r180 top
C68 "C1608X7R1H104K" 0603 1501.3,3940 r180 top
C70 "C1608X7R1H104K" 0603 1484.73,-485.55 r0 top
C71 "C1608X7R1H104K" 0603 2160,4215 r180 top
C72 "CGA3E2C0G1H103J080AA" 0603 2670,3745 r270 top
C73 "CGA3E2C0G1H103J080AA" 0603 2670,2545 r270 top
C74 "CGA3E2C0G1H103J080AA" 0603 2670,1345 r270 top
C75 "CGA3E2C0G1H103J080AA" 0603 2670,732 r270 top
C76 "CGA3E2C0G1H103J080AA" 0603 2670,1945 r270 top
C77 "CGA3E2C0G1H103J080AA" 0603 2670,3145 r270 top
C78 "CGA3E2C0G1H103J080AA" 0603 5654,5686.5 r90 top
C79 "C1608X7R1H104K" 0603 2270,-490 r0 top
C80 "C2012X7R1V475K125AC" 0805_HV 2025,4320 r90 top
C81 "GRM1885C1H470JA01D" 0603 2030,-739.5 r90 top
C82 "C1608X7R1H104K" 0603 2062.27,-835.95 r180 top
C83 "GRM1885C1H470JA01D" 0603 2029.73,4501.58 r90 top
C84 "GRM1885C1H470JA01D" 0603 2029.5,946 r90 top
C85 "C2012X7R1V475K125AC" 0805_HV 2039.77,775.55 r90 top
C87 "C1608X7R1H104K" 0603 1945,4330 r90 top
C89 "C1608X7R1H104K" 0603 1959.77,770.55 r90 top
C91 "C1608X7R1H104K" 0603 2074.73,-430.55 r180 top
C92 "GRM1885C1H470JA01D" 0603 2044.73,-335.55 r90 top
C94 "C1608X7R1H104K" 0603 2303,-651.5 r90 top
C95 "C2012X7R1V475K125AC" 0805_HV 2577.33,-617.68 r270 top
C96 "C2012X7R1V475K125AC" 0805_HV 2747.33,-426.68 r0 top
C97 "C1608X7R1H104K" 0603 2733.33,-502.68 r0 top
C101 "GRM1885C1H120JA01D" 0603 1531.3,3225 r270 top
C102 "GRM1885C1H120JA01D" 0603 1531.3,3845 r270 top
C103 "GRM1885C1H120JA01D" 0603 1530.3,1990 r270 top
C104 "GRM1885C1H120JA01D" 0603 1531.3,2606.97 r270 top
C105 "GRM1885C1H120JA01D" 0603 1531.3,237 r270 top
C106 "GRM1885C1H120JA01D" 0603 1531.3,1371.97 r270 top
C111 "B32774D1305K000" B32774_3150x1800x2750 3900,-515 r180 top
C112 "B32774D1305K000" B32774_3150x1800x2750 3900,5010 r180 top locked
C162 "CGA3E2NP01H101J080AA" 0603 1265,1438 r90 top
C163 "CGA3E2NP01H101J080AA" 0603 1463,236 r270 top
C164 "CGA3E2NP01H101J080AA" 0603 1363,3910 r90 top
C165 "CGA3E2NP01H101J080AA" 0603 1411,3226 r270 top
C166 "CGA3E2NP01H101J080AA" 0603 1286.73,2676.45 r90 top
C167 "CGA3E2NP01H101J080AA" 0603 1432.82,1991.09 r270 top
"CAUTION HOT SURFACE" "CAUTION HOT SURFACE" IEC_HotSurface_Medium 3826,2420 r0 top
D1 "B0530W-7-F" SOD-123 207,3960 r180 top
D2 "MSS2P3-M3/89A" MicroSMP 2005,3155 r90 top
D3 "MSS2P3-M3/89A" MicroSMP 2005,3775 r90 top
D4 "MSS2P3-M3/89A" MicroSMP 2005,1301.97 r90 top
D5 "MSS2P3-M3/89A" MicroSMP 2005,167 r90 top
D6 "MSS2P3-M3/89A" MicroSMP 2005,2536.97 r90 top
D7 "MSS2P3-M3/89A" MicroSMP 2004,1920 r90 top
D9 "RHRG30120" TO-247-2 5821.27,5039 r90 bottom
D10 "1SMB5956BT3G" SMB 4085.74,-300.55 r180 bottom
D11 "1SMB5956BT3G" SMB 3781.74,-300.55 r180 bottom
D12 "BYG23T-M3/TR" SMA 2344,1417 r0 bottom
D13 "BYG23T-M3/TR" SMA 2255,2650 r0 bottom
D14 "BYG23T-M3/TR" SMA 2258,3887 r0 bottom
"ESD Sensitive" "ESD Susceptible" ESD_Overlay_Medium 899,3767 r0 top
FID1 "Fiducial" Fiducial10-20 720,4855 r270 top
FID2 "Fiducial" Fiducial10-20 845,100 r90 top
FID3 "Fiducial" Fiducial10-20 5319.53,-855 r90 bottom
FID4 "Fiducial" Fiducial10-20 5315,-855 r90 top
FID5 "Fiducial" Fiducial10-20 845,100 r90 bottom
FID6 "Fiducial" Fiducial10-20 720,4855 r270 bottom
H1 "MH 3.2mm" MH3.2_H5_W6_KO8_STARHEAD 200,200 r180 top locked
H2 "MH 3.2mm" MH3.2_H5_W6_KO8_STARHEAD 200,4760.63 r180 top locked
H3 "MH 3.2mm" MH3.2_H5_W6_KO8_STARHEAD 6375,3805 r180 top
H4 "MH 3.2mm" MH3.2_H5_W6_KO8_STARHEAD 6375,-780 r180 top
H5 "1902C" Keystone_1902C 6375,3805 r0 bottom
H6 "1902C" Keystone_1902C 6375,-780 r0 bottom
H7 "1902C" Keystone_1902C 200,4760.63 r0 bottom
H8 "1902C" Keystone_1902C 200,200 r0 bottom
J1 "5747461-1" Amp_DB25 397,2485 r90 top locked
J2 "282834-2" TEC_282834-2 129.73,4161.45 r270 top
J3 "1902547" Phoenix_1902547 6228.05,4457.6 r90 top
J4 "1904150" Phoenix_1904150 6241.05,2395 r90 top
J5 "800-10-003-10-001000" Mill-Max_800-10-003-10-001000 2125,4095 r0 top
J6 "800-10-003-10-001000" Mill-Max_800-10-003-10-001000 2125,1621 r0 top
J7 "800-10-003-10-001000" Mill-Max_800-10-003-10-001000 2125,461 r180 top
J8 "1902547" Phoenix_1902547 6231,5285 r90 top
J13 "800-10-003-10-001000" Mill-Max_800-10-003-10-001000 2125,2860 r0 top
LBL1 "Size: 0.65\" x 0.20 \"" Label_650x200 5462,-611 r0 top
Logo2 "Pb-Free Symbol" Pb-Free_Overlay_Small 5905,-607 r0 top
Logo3 "FCC disclaimer" FCC_disclaimer 6228,88 r0 top
LOGO4 "HIGH VOLTAGE" IEC_HighVoltage_medium 6207,1393 r0 top
LOGO5 "HIGH VOLTAGE" IEC_HighVoltage_medium 2604,5097 r0 top
LOGO6 "HIGH VOLTAGE" IEC_HighVoltage_medium 3499,526 r0 top
LOGO7 "HIGH VOLTAGE" IEC_HighVoltage_medium 5364,5525 r0 top
Q1 "NGTB25N120IHLWG" TO-247 5841,5686 r90 bottom
R1 "CRCW12060000Z0EA" 1206 689,1603 r90 top
R2 "CRCW06030000Z0EA" 0603 2045,3950 r90 top
R3 "CRCW12060000Z0EA" 1206 2175,3915 r0 top
R4 "CRCW06030000Z0EA" 0603 1980,3950 r90 top
R5 "CRCW06030000Z0EA" 0603 2045,3330 r90 top
R6 "CRCW12060000Z0EA" 1206 683,3365 r270 top
R7 "CRCW060322R0JNEA" 0603 909,2763 r90 top
R8 "CRCW06031K00FKEA" 0603 1461.3,5145 r270 top
R9 "CRCW12060000Z0EA" 1206 2175,3295 r0 top
R10 "CRCW06030000Z0EA" 0603 1980,3330 r90 top
R11 "RC1206FR-0712RL" 1206 2175,3190 r0 top
R12 "CRCW060310K0JNEA" 0603 2601,732 r90 top
R13 "RC1206FR-0712RL" 1206 2175,3085 r0 top
R14 "CRCW06030000Z0EA" 0603 2045,1476.97 r90 top
R15 "CRCW12060000Z0EA" 1206 2175,1440.97 r0 top
R16 "CRCW06030000Z0EA" 0603 1980,1476.97 r90 top
R17 "RC1206FR-0712RL" 1206 2175,3810 r0 top
R18 "RC1206FR-0712RL" 1206 2175,1336.97 r0 top
R19 "RC1206FR-0712RL" 1206 2175,3705 r0 top
R20 "CRCW060310K0JNEA" 0603 2605,3745 r90 top
R21 "RC1206FR-0712RL" 1206 2175,1231.97 r0 top
R22 "CRCW06030000Z0EA" 0603 2045,342 r90 top
R23 "CRCW12060000Z0EA" 1206 2175,307 r0 top
R24 "CRCW06030000Z0EA" 0603 1981,342 r90 top
R25 "RC1206FR-0712RL" 1206 2175,202 r0 top
R26 "CRCW060310K0JNEA" 0603 2605,3145 r90 top
R27 "RC1206FR-0712RL" 1206 2175,97 r0 top
R28 "CRCW06030000Z0EA" 0603 2045,2711.97 r90 top
R29 "CRCW12060000Z0EA" 1206 2175,2675.97 r0 top
R30 "CRCW06030000Z0EA" 0603 1980,2711.97 r90 top
R31 "RC1206FR-0712RL" 1206 2175,2571.97 r0 top
R32 "CRCW060310K0JNEA" 0603 2605,2545 r90 top
R33 "RC1206FR-0712RL" 1206 2175,2466.97 r0 top
R34 "CRCW06030000Z0EA" 0603 2044,2095 r90 top
R35 "CRCW12060000Z0EA" 1206 2174,2060 r0 top
R36 "CRCW06030000Z0EA" 0603 1980,2095 r90 top
R37 "RC1206FR-0712RL" 1206 2174,1955 r0 top
R38 "CRCW060310K0JNEA" 0603 2605,1945 r90 top
R39 "RC1206FR-0712RL" 1206 2174,1850 r0 top
R40 "CRCW06030000Z0EA" 0603 2285,-325 r180 top
R41 "CRCW12061R00FKEA" 1206 2053.37,1361.97 r90 bottom
R42 "CRCW12061R00FKEA" 1206 2053.37,2596.97 r90 bottom
R43 "CRCW12061R00FKEA" 1206 2053.37,3835 r90 bottom
R44 "CRCW12060000Z0EA" 1206 329,1364 r180 top
R45 "CRCW1206100KJNEAHP" 1206L 4660,5283.69 r180 bottom
R46 "CRCW060322R0JNEA" 0603 1397.95,911.55 r180 top
R47 "CRCW060322R0JNEA" 0603 1397.95,974.55 r180 top
R48 "CRCW1206100KJNEAHP" 1206L 4481.5,5283.69 r180 bottom
R49 "CRCW1206100KJNEAHP" 1206L 4303,5283.69 r180 bottom
R50 "CRCW1206100KJNEAHP" 1206L 4124.5,5283.69 r180 bottom
R51 "CRCW1206100KJNEAHP" 1206L 3589,5283.69 r0 bottom
R52 "CRCW060322R0JNEA" 0603 1364.5,4476 r180 top
R53 "CRCW060322R0JNEA" 0603 1364.5,4539 r180 top
R54 "CRCW1206100KJNEAHP" 1206L 3767.5,5283.69 r0 bottom
R55 "CRCW060322R0JNEA" 0603 1366.5,-773 r180 top
R56 "CRCW060322R0JNEA" 0603 1366.5,-711 r180 top
R57 "CRCW1206100KJNEAHP" 1206L 3946,5283.69 r0 bottom
R58 "CRCW060322R0JNEA" 0603 1398.5,-367 r180 top
R59 "CRCW060322R0JNEA" 0603 1398.5,-304 r180 top
R71 "CRCW120616R5FKEA" 1206 2023.35,5205.25 r0 top
R79 "CRCW06030000Z0EA" 0603 2124.5,976 r180 top
R80 "CRCW06030000Z0EA" 0603 2124.5,916 r180 top
R81 "CRCW060312K1FKEA" 0603 2130,-639.5 r0 top
R82 "CRCW06030000Z0EA" 0603 2130,-704.5 r180 top
R83 "CRCW06030000Z0EA" 0603 2130,-769.5 r180 top
R85 "CRCW06030000Z0EA" 0603 2129.73,4536.58 r180 top
R86 "CRCW06030000Z0EA" 0603 2129.73,4471.58 r180 top
R90 "CRCW06031K00FKEA" 0603 2144.73,-180.55 r180 top
R91 "CRCW06030000Z0EA" 0603 2144.73,-240.55 r0 top
R92 "CRCW06030000Z0EA" 0603 2144.73,-305.55 r180 top
R93 "CRCW06030000Z0EA" 0603 2145,-370 r180 top
R94 "CRCW120616R5FKEA" 1206 2024.35,5099.25 r0 top
R96 "CRCW060310K0JNEA" 0603 5589,5686.5 r270 top
R98 "RC1206FR-07820KL" 1206 4115,-480 r0 bottom
R99 "CRCW06030000Z0EA" 0603 1885,1548.97 r180 bottom
R100 "CRCW06030000Z0EA" 0603 1885,4022 r180 bottom
R101 "CRCW06030000Z0EA" 0603 1888,405 r180 bottom
R102 "CRCW06030000Z0EA" 0603 1885,3393 r180 bottom
R103 "CRCW06030000Z0EA" 0603 1885,2783.97 r180 bottom
R105 "CRCW06030000Z0EA" 0603 1887,2158 r180 bottom
R106 "CRCW0603160KFKEA" 0603 2284.45,-259.73 r0 top
R107 "CRCW06031K00FKEA" 0603 2238,-651.5 r90 top
R108 "RC1206FR-07820KL" 1206 3750,-480 r0 bottom
R109 "CRCW06031K00FKEA" 0603 3213,-547.5 r270 bottom
R110 "CRCW06030000Z0EA" 0603 2733.33,-350.68 r180 top
R112 "CRCW060310K0JNEA" 0603 2605,1345 r90 top
R118 "PU5931FKMP70R004L" PU5931_146 5470,3300 r0 top
R120 "PU5931FKMP70R004L" PU5931_146 5470,1495 r0 top
R122 "RC1206FR-07820KL" 1206 3685,-660 r90 bottom
R125 "RC1206FR-07820KL" 1206 3630,-860 r0 bottom
R127 "RC1206FR-07820KL" 1206 3417.91,-860 r0 bottom
R128 "RC1206FR-07820KL" 1206 3210,-860 r0 bottom
R129 "RC1206FR-07820KL" 1206 3153,-710 r270 bottom
R139 "CRCW06031K00FKEA" 0603 1212,3257 r180 top
R140 "CRCW06031K00FKEA" 0603 1239,3843 r270 top
R141 "CRCW06031K00FKEA" 0603 1127.82,2024.1 r180 top
R142 "CRCW06031K00FKEA" 0603 1219,2610 r270 top
R143 "CRCW06031K00FKEA" 0603 1143,1406 r180 top
R144 "CRCW06031K00FKEA" 0603 1304,273 r180 top
R150 "ERJ-3GEY0R00V" 0603 1466,535 r90 bottom
R151 "ERJ-3GEY0R00V" 0603 1465.37,1196 r90 top
R154 "ERJ-3GEY0R00V" 0603 1483,3538 r270 bottom
R155 "ERJ-3GEY0R00V" 0603 1467,3669 r90 top
R158 "ERJ-3GEY0R00V" 0603 1482,2301 r270 bottom
R159 "ERJ-3GEY0R00V" 0603 1466.37,2429 r90 top
R162 "ERJ-3EKF1002V" 0603 1347.27,1437.05 r270 top
R163 "ERJ-3EKF1002V" 0603 1397,236 r90 top
R164 "ERJ-3EKF1002V" 0603 1299,3911 r270 top
R165 "ERJ-3EKF1002V" 0603 1348.3,3225.81 r90 top
R166 "ERJ-3EKF1002V" 0603 1375,2673 r270 top
R167 "ERJ-3EKF1002V" 0603 1348.82,1991.1 r90 top
R168 "ERJ-3GEY0R00V" 0603 1561.8,1227.5 r180 top
R169 "ERJ-3GEY0R00V" 0603 1561.8,88.5 r180 top
R170 "ERJ-3GEY0R00V" 0603 1562.5,3700.5 r180 top
R171 "ERJ-3GEY0R00V" 0603 1562.5,3076.5 r180 top
R172 "ERJ-3GEY0R00V" 0603 1562.8,2460.8 r180 top
R173 "ERJ-3GEY0R00V" 0603 1562.5,1845.5 r180 top
TP1 "5000" Keystone5000 1161,-678 r90 top
TP2 "5000" Keystone5000 1161,-828 r90 top
TP3 "5000" Keystone5000 1254,-250 r90 top
TP4 "5000" Keystone5000 777,4110 r90 top
TP5 "5000" Keystone5000 1340,4660 r90 top
TP6 "5000" Keystone5000 1325,4375 r90 top
TP7 "5000" Keystone5000 2577,-474 r90 top
TP10 "5000" Keystone5000 1263,1022 r90 top
TP11 "5000" Keystone5000 1263,877 r90 top
TP12 "TESTPOINT" TP_VIA_060RND040 2890,3850 r90 top
TP13 "TESTPOINT" TP_VIA_060RND040 2890,3635 r90 top
TP14 "TESTPOINT" TP_VIA_060RND040 2890,2650 r90 top
TP15 "5000" Keystone5000 1263,-425 r90 top
TP16 "TESTPOINT" TP_VIA_060RND040 2890,2435 r90 top
TP17 "TESTPOINT" TP_VIA_060RND040 2890,1450 r90 top
TP18 "TESTPOINT" TP_VIA_060RND040 2890,1235 r90 top
TP19 "TESTPOINT" TP_VIA_060RND040 2890,850 r90 top
TP20 "TESTPOINT" TP_VIA_060RND040 2890,635 r90 top
TP21 "TESTPOINT" TP_VIA_060RND040 2890,2040 r90 top
TP22 "TESTPOINT" TP_VIA_060RND040 2890,1825 r90 top
TP23 "TESTPOINT" TP_VIA_060RND040 2890,3250 r90 top
TP24 "TESTPOINT" TP_VIA_060RND040 2890,3035 r90 top
TP25 "TESTPOINT" TP_VIA_060RND040 4040,160 r180 top
TP26 "TESTPOINT" TP_VIA_060RND040 4040,4384 r180 top
TP27 "TESTPOINT" TP_VIA_060RND040 4485,3606 r180 top
TP28 "TESTPOINT" TP_VIA_060RND040 4755,3450 r180 top
TP29 "5000" Keystone5000 5260,3560 r180 top
TP30 "TESTPOINT" TP_VIA_060RND040 2889,3554 r180 top
TP31 "5000" Keystone5000 5260,2548 r90 top
TP32 "5000" Keystone5000 5260,1760 r90 top
TP33 "TESTPOINT" TP_VIA_060RND040 3770,160 r180 top
TP34 "TESTPOINT" TP_VIA_060RND040 3770,4384 r180 top
TP35 "TESTPOINT" TP_VIA_060RND040 2983,3348 r90 top
TP36 "5000" Keystone5000 2428,-219 r270 top
TP37 "5000" Keystone5000 2410,-540 r90 top
U1 "UCC5350MCD" D0008B_HV 1730,3850 r0 top
U2 "UCC5350MCD" D0008B_HV 1730,3230 r0 top
U3 "TLV1117-33IDRJR" DRJ0008A 602,4125 r0 top
U4 "SN74LVC1G17DCKR" DCK0005A_N 799,2758 r0 top
U5 "UCC5350MCD" D0008B_HV 1730,1376.97 r0 top
U6 "UCC5350MCD" D0008B_HV 1730,242 r0 top
U7 "UCC5350MCD" D0008B_HV 1730,2611.97 r0 top
U8 "UCC5350MCD" D0008B_HV 1729,1995 r0 top
U9 "TLV521" DCK0005A_N 2280,-405 r180 top
U10 "UCC5350MCD" D0008B_HV 1730,5150 r0 top
U12 "AMC1306E25DWVR" DWV0008A 1729.73,-763.55 r180 top
U13 "AMC1306E25DWVR" DWV0008A 1729.73,4501.58 r180 top
U14 "AMC1306E25DWVR" DWV0008A 1729.5,946 r180 top
U15 "AMC1306E25DWVR" DWV0008A 1729.73,-335.55 r180 top
U20 "LM3480IM3-5.0/NOPB" MF03A_N 2155,4315 r0 top
U22 "LM3480IM3-5.0/NOPB" MF03A_N 2174.77,765.55 r0 top
U23 "TLV70433DBVR" DBV0005A_N 2702.33,-632.68 r270 top
U24 "CM100TX-24S1" CM100TX-24S1 3901.89,2249.76 r270 bottom locked
XF1 "3566" Keystone_3566 3491.5,5722 r0 top
XF2 "3566" Keystone_3566 4613.16,5722 r0 top
ZZ1 "This Assembly Note is for PCB labels only" AssemblyNoteLabel -845.27,6629.45 r0 top
ZZ2 "These assemblies are ESD sensitive, ESD precautions shall be observed." AssemblyNote 509.73,9185.45 r0 top
ZZ3 "These assemblies must be clean and free from flux and all contaminants. Use of no clean flux is not acceptable." AssemblyNote 509.73,9100.45 r0 top
ZZ4 "These assemblies must comply with workmanship standards IPC-A-610 Class 2, unless otherwise specified." AssemblyNote 509.73,9025.45 r0 top

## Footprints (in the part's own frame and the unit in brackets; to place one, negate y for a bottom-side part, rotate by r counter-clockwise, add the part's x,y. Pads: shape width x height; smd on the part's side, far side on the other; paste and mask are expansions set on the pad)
0603 [mm] "0603 from SM-752 data"
  rect 1x0.95 smd: 1(-0.8,0) 2(0.8,0)
  silkscreen extent -1.52,-0.69 1.52,0.69, body extent -0.87,-0.47 0.87,0.47, height 1
0805_HV [mil] "0805 with 30mil clearance between pads"
  rect 50x63 smd: 1(-40,0) 2(40,0)
  silkscreen extent -74,-40 74,40, body extent -43,-29 43,29, height 57
1206 [mm] "1206 from SM-752 data"
  rect 1.3x1.85 smd: 1(-1.45,0) 2(1.45,0)
  silkscreen extent -2.4,-1.21 2.4,1.21, body extent -1.7,-0.9 1.7,0.9, height 1.35
1206L [mm] "1206 from SM-752 data"
  rect 1.1x1.75 smd: 1(-1.35,0) 2(1.35,0)
  silkscreen extent -0.4,-0.77 0.4,0.77, body extent -1.7,-0.9 1.7,0.9, height 1.35
1210_270 [mm] "1210"
  rect 1.3x2.7 smd: 1(-1.45,0) 2(1.45,0)
  silkscreen extent -2.32,-1.57 2.32,1.57, body extent -1.7,-1.35 1.7,1.35, height 2.7
1210_280 [mm] "SMD, 2-Leads, Body 3.6x2.8mm, Height 2.8mm"
  rect 1.1x2.2 smd: 1(-1.65,0) 2(1.65,0)
  silkscreen extent -0.84,-1.4 0.84,1.4, body extent -1.8,-1.4 1.8,1.4, height 2.8
Amp_DB25 [mil] "Amp 5747461-1"
  rect 75x75 hole 41: 1(-654,-193.5)
  round 75 hole 41: 2(-545,-193.5) 3(-436,-193.5) 4(-327,-193.5) 5(-218,-193.5) 6(-109,-193.5) 7(0,-193.5) 8(109,-193.5) 9(218,-193.5) 10(327,-193.5) 11(436,-193.5) 12(545,-193.5) 13(654,-193.5) 14(-599.5,-81.5) 15(-490.5,-81.5) 16(-381.5,-81.5) 17(-272.5,-81.5) 18(-163.5,-81.5) 19(-54.5,-81.5) 20(54.5,-81.5) 21(163.5,-81.5) 22(272.5,-81.5) 23(381.5,-81.5) 24(490.5,-81.5) 25(599.5,-81.5)
  round 200 hole 120: 26(-928,193.5) 27(928,193.5)
  silkscreen extent -1066,-298 1060,407, body extent -1042,-221 1048,751, height 455
AssemblyNote [mil] "Assembly Note"
AssemblyNoteLabel [mil] "Assembly Note for PCB Labels"
B32774_3150x1800x2750 [mm] "TH, 2-Leads, Body 31.5x18mm, Pin Spacing 27.5mm"
  round 1.6 hole 1.1: 1(-13.75,0) 2(13.75,0)
  silkscreen extent -15.75,-9 15.75,9, body extent -15.75,-9 15.75,9, height 27.5
CM100TX-24S1 [mm] "TH, 35-Leads, Body 121.7x62mm"
  rrect50% 2.2x2.2 hole 1.7: 1(-40.01,28.975)
  round 2.2 hole 1.7: 2(-36.19,28.975) 3(-24.77,28.975) 4(-20.95,28.975) 5(-9.53,28.975) 6(-5.71,28.975) 7(5.71,28.975) 8(9.53,28.975) 9(20.95,28.975) 10(24.77,28.975) 11(36.19,28.975) 12(40.01,28.975) 13(59.055,13.34) 14(59.055,9.53) 15(59.055,5.71) 16(59.055,-5.71) 17(59.055,-9.52) 18(59.055,-13.34) 19(41.91,-28.975) 20(38.1,-28.975) 21(22.86,-28.975) 22(19.05,-28.975) 23(15.24,-28.975) 24(0,-28.975) 25(-3.81,-28.975) 26(-7.62,-28.975) 27(-22.86,-28.975) 28(-26.67,-28.975) 29(-30.48,-28.975) 30(-59.055,-13.34) 31(-59.055,-9.53) 32(-59.055,-5.71) 33(-59.055,5.71) 34(-59.055,9.53) 35(-59.055,13.34)
  round 0 hole 2.6 unplated mask+1.473: MH1(-47.25,28.75) MH2(47.25,28.75) MH3(-47.25,-28.75) MH4(47.25,-28.75)
  silkscreen extent -60.85,-31 60.85,31.9, body extent -60.85,-31 60.85,31, height 17
D0008B_HV [mm] "SOIC, 8-Leads, Body 4.9x3.9mm, Pitch 1.27mm, HV / Isolation option"
  rrect17% 1.4x0.6 smd: 1(-2.75,1.905) 2(-2.75,0.635) 3(-2.75,-0.635) 4(-2.75,-1.905) 5(2.75,-1.905) 6(2.75,-0.635) 7(2.75,0.635) 8(2.75,1.905)
  silkscreen extent -3.3,-2.5 0.9,2.5, body extent -3,-2.45 3,2.45, height 1.63
DBV0005A_N [mm] "SOT23, 5-Leads, Body 2.9x1.6mm, Pitch 0.95mm, Lead Span 2.8mm, IPC Medium Density"
  rrect17% 1x0.6 smd: 1(-1.375,0.95) 2(-1.375,0) 3(-1.375,-0.95) 4(1.375,-0.95) 5(1.375,0.95)
  silkscreen extent -1.63,-1.55 0.38,1.55, body extent -1.42,-1.46 1.42,1.46, height 1.09
DCK0005A_N [mm] "SOT353, 5-Leads, Body 2x1.3mm, Pitch 0.65mm, Lead Span 2.1mm, IPC Medium Density"
  rrect25% 0.85x0.4 smd: 1(-1.125,0.65) 2(-1.125,0) 3(-1.125,-0.65) 4(1.125,-0.65) 5(1.125,0.65)
  silkscreen extent -1.48,-1.02 0.55,1.1, body extent -1.14,-1 1.14,1, height 0.95
DRJ0008A [mm] "SON, 8-Leads, Body 4x4mm, Pitch 0.8mm, Thermal Pad 3x2.2mm, TI Recommended"
  oval 0.7x0.3 smd: 1(-1.9,1.2) 2(-1.9,0.4) 3(-1.9,-0.4) 4(-1.9,-1.2) 5(1.9,-1.2) 6(1.9,-0.4) 7(1.9,0.4) 8(1.9,1.2)
  rect 2.2x3 smd paste-1.1: 9(0,0)
  silkscreen extent -2.2,-2.2 2.2,2.2, body extent -2.05,-2.05 2.05,2.05, height 0.81
DWV0008A [mm] "SOIC, 8-Leads, Body 5.95x7.6mm (max), Pitch 1.27mm"
  rrect17% 1.8x0.6 smd: 1(-5.45,1.905) 2(-5.45,0.635) 3(-5.45,-0.635) 4(-5.45,-1.905) 5(5.45,-1.905) 6(5.45,-0.635) 7(5.45,0.635) 8(5.45,1.905)
  silkscreen extent -6.25,-2.95 2.98,2.95, body extent -5.77,-2.92 5.77,2.93, height 2.67
ESD_Overlay_Medium [mil]
  silkscreen extent -127,-109 125,110
FCC_disclaimer [mil]
Fiducial10-20 [mm]
  round 1 smd mask+0.5: 1(0,0)
  Top Layer keep-out circle w1.178: c0,0 r0.5
IEC_HighVoltage_medium [mil]
  silkscreen extent -217,-176 217,200
IEC_HotSurface_Medium [mil]
  silkscreen extent -217,-188 217,188
Keystone5000 [mil] "For Keystone 500x miniature loop terminals"
  round 80 hole 40: 1(0,0)
  silkscreen extent -58,-58 58,58, body extent -49,-49 49,49, height 182
Keystone_1902C [mil] "Hex Standoff, 4-40 threaded, nylon"
  round 1 on Mech4: 0(0,0)
  body extent -145,-126 146,126, height 501
Keystone_3566 [mm] "Keyston"
  round 2.85 hole 2.25: 1(-5.245,0) 2(5.245,0)
  silkscreen extent -5.61,-6.22 5.61,6.22, body extent -5.63,-6.14 5.63,6.14, height 18.98
Label_650x200 [mil] "Thermal Transfer Label"
  round 1 on Mech13: 0(0,0)
  silkscreen extent -325,-100 325,100, body extent -325,-100 325,100, height 1
MF03A_N [mm] "SOT23, 3-Leads, Body 2.9x1.3mm, Pitch 0.95mm, Lead Span 2.4mm, IPC Medium Density"
  rect 1.3x0.6 smd: 1(-1.05,0.95) 2(-1.05,-0.95) 3(1.05,0)
  silkscreen extent -1.17,-1.5 0.7,1.92, body extent -0.7,-1.5 0.7,1.5, height 1.12
MH3.2_H5_W6_KO8_STARHEAD [mil]
  round 20 / inner round 142 / far side round 20 hole 128 unplated mask+65: 1(0,0)
  Keep-Out Layer region: 160.49,0 158.52,25.11 152.64,49.6 143,72.86 129.84,94.34 113.49,113.49 94.34,129.84 72.86,143 49.6,152.64 25.11,158.52 0,160.49 -25.11,158.52 -49.6,152.64 -72.86,143 -94.34,129.84 -113.49,113.49 -129.84,94.34 -143,72.86 -152.64,49.6 -158.52,25.11 -160.49,0 -158.52,-25.11 -152.64,-49.6 -143,-72.86 -129.84,-94.34 -113.49,-113.49 -94.34,-129.84 -72.86,-143 -49.6,-152.64 -25.11,-158.52 0,-160.49 25.11,-158.52 49.6,-152.64 72.86,-143 94.34,-129.84 113.49,-113.49 129.84,-94.34 143,-72.86 152.64,-49.6 158.52,-25.11
  silkscreen extent -120,-120 120,120
MicroSMP [mm] "SMD, 2-Leads, Body 2.2x1.3mm"
  rect 2x1.1 smd: 1(-0.65,0)
  rect 0.8x0.8 smd: 2(1.25,0)
  silkscreen extent -2.2,-1 1.6,1, body extent -1.15,-0.7 1.15,0.7, height 0.75
Mill-Max_800-10-003-10-001000 [mm] "Mill-Max"
  rect 1.5x1.5 hole 0.85: 1(-2.54,0)
  round 1.5 hole 0.85: 2(0,0) 3(2.54,0)
  silkscreen extent -3.81,-1.27 3.81,1.78, body extent -3.81,-1.27 3.81,1.27, height 8.13
Pb-Free_Overlay_Small [mil]
  silkscreen extent -46,-46 46,46
Phoenix_1902547 [mm] "TH, 2-Leads, Body 19.04x16mm, Pitch 9.52mm"
  rect 1.8x1.8 hole 1.3: 1(-4.76,3.1)
  round 1.8 hole 1.3: 2(4.76,3.1)
  silkscreen extent -10,-8 10.09,8, body extent -9.52,-8 10.09,8, height 22
Phoenix_1904150 [mm] "TH, 3-Leads, Body 28.56x16mm, Pitch 9.52mm"
  rect 1.8x1.8 hole 1.3: 1(-9.52,3.1)
  round 1.8 hole 1.3: 2(0,3.1) 3(9.52,3.1)
  silkscreen extent -14.8,-8 14.85,8, body extent -14.28,-8 14.85,8, height 22
PU5931_146 [mm] "SMD, 2-Leads, Body 15x7.75mm"
  rect 5.2x8.75 smd: 1(-5.4,0) 2(5.4,0)
  silkscreen extent -2.4,-3.88 2.4,3.87, body extent -7.5,-3.87 7.5,3.88, height 1.46
SMA [mm] "Molded Diode, 2-Leads, Body 4.3x2.6mm, IPC Medium Density, based on OnSemi component dimensions and land pattern"
  rect 2x2 smd: 1(-2,0) 2(2,0)
  silkscreen extent -3.66,-1.57 2.79,1.57, body extent -2.6,-1.3 2.6,1.3, height 2.42
SMB [mil] "Molded Diode, 2-Leads, Body 5.4x3.6mm, IPC Medium Density, based on OnSemi component dimensions"
  rect 85x107.99 smd: 1(-87.01,0) 2(87.01,0)
  silkscreen extent -155,-82 125,82, body extent -106,-71 106,71, height 91
SOD-123 [mm] "On Semi recommended land pattern"
  rect 0.915x1.22 smd: 1(-1.637,0) 2(1.637,0)
  silkscreen extent -2.74,-1.17 2.03,1.17, body extent -1.93,-0.9 1.93,0.9, height 1.35
TEC_282834-2 [mm] "TEC"
  rect 1.6x1.6 hole 1.1: 1(-1.27,0)
  round 1.6 hole 1.1: 2(1.27,0)
  silkscreen extent -3.66,-3.4 2.9,3.4, body extent -2.77,-3.25 2.77,3.25, height 10.01
TO-247 [mil] "Standard TO-247"
  rect 95x95 hole 62: 1(-215,0)
  round 95 / inner round 74.8 / far side round 96 hole 62: 2(0,0) 3(215,0)
  silkscreen extent -318,-124 318,81, body extent -318,-124 318,81, height 1007
TO-247-2 [mm] "TH, 2-Leads, Body 15.75x4.95mm, Pin Spacing 10.16mm"
  round 2.6 hole 2.1: 1(-5.08,-0.21) 2(5.08,-0.21)
  silkscreen extent -8.01,-2.61 8.01,2.61, body extent -8.01,-2.61 8,2.6, height 23.77
TP_VIA_060RND040 [mil] "TP_VIA_060RND040"
  round 60 hole 40: 1(0,0)

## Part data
C1 C4 C7 C9 C12 C15 C18 C19 C22 C26 C28 C29 C33 C35 C37 C38 C41 C43 C44 C47 C49 C57 C58 C59 C61 C62 C64 C67 C80 C85 C95 C96: "CAP, CERM, 4.7 µF, 35 V, +/- 10%, X7R, 0805"
C2 C6 C8 C11 C14 C17 C21 C25 C27 C30 C36 C42 C63 C65 C66 C68 C70 C71 C79 C82 C87 C89 C91 C94 C97: "CAP, CERM, 0.1 µF, 50 V, +/- 10%, X7R, 0603"
C3 C13 C16 C20 C23 C31 C32 C34 C39 C40 C45 C46 C48 C50 C51 C52 C53 C54 C56: "CAP, CERM, 0.47 µF, 50 V, +/- 10%, X7R, 0603"
C5: "CAP, CERM, 10 µF, 50 V, +/- 10%, X7R, 1210"
C10 C101 C102 C103 C104 C105 C106: "CAP, CERM, 12 pF, 50 V, +/- 5%, C0G/NP0, 0603"
C24: "CAP, CERM, 100 µF, 16 V, +/- 20%, X5R, 1210"
C72 C73 C74 C75 C76 C77 C78: "CAP, CERM, 0.01 µF, 50 V, +/- 5%, C0G/NP0, AEC-Q200 Grade 1, 0603"
C81 C83 C84 C92: "CAP, CERM, 47 pF, 50 V, +/- 5%, C0G/NP0, 0603"
C111 C112: "CAP, Film, 3 µF, 1300 V, +/- 10%, 0.016 ohm, TH"
C162 C163 C164 C165 C166 C167: "CAP, CERM, 100 pF, 50 V,+/- 5%, C0G/NP0, AEC-Q200 Grade 0, 0603"
"CAUTION HOT SURFACE": library part IEC_HotSurface, "IEC 61010-1 Hot Surface Warning"
D1: "Diode, Schottky, 30 V, 0.5 A, SOD-123"
D2 D3 D4 D5 D6 D7: library part MSS1P3L-M3/89A, "Diode, Schottky, 30 V, 2 A, AEC-Q101, MicroSMP"
D9: library part FFH60UP40S, "Diode, Ultrafast, 1200 V, 30 A, TH"
D10 D11: "Diode, Zener, 200 V, 550 mW, SMB"
D12 D13 D14: "Diode, Ultrafast, 1300 V, 1 A, SMA"
"ESD Sensitive": library part ESD_Susceptible, "ESD Susceptible Symbol"
FID1 FID2 FID3 FID4 FID5 FID6: "Fiducial mark.  There is nothing to buy or mount."
H1 H2 H3 H4: library part "MH 3_0.5MM", "Mountin hole, NPTH Drill 3.2mm"
H5 H6 H7 H8: "Standoff, Hex, 0.5\"L #4-40 Nylon"
J1: "Connector, TH, DB25 parallel port, plastic, right angle"
J2: "Terminal Block, 2x1, 2.54mm, TH"
J3 J8: "Terminal Block, 9.52mm, 2x1, R/A, TH"
J4: "Terminal Block, 9.52mm, 3x1, R/A, TH"
J5 J6 J7 J13: "Header, 100mil, 3x1, TH"
LBL1: library part THT-14-423-10, "Thermal Transfer Printable Labels, 0.650\" W x 0.200\" H - 10,000 per roll"
Logo2: library part Pb-Free
Logo3: library part FCC_disclaimer, "FCC_disclaimer"
LOGO4 LOGO5 LOGO6 LOGO7: library part IEC_HighVoltage, "IEC 61010-1 High Voltage Warning"
Q1: library part "IGW03N120H2, Infineon Technologies", "Transistor, IGBT, 1200 V, 9.9 A, TO-247"
R1 R3 R6 R9 R15 R23 R29 R35 R44: "RES, 0, 5%, 0.25 W, 1206"
R2 R4 R5 R10 R14 R16 R22 R24 R28 R30 R34 R36 R40 R79 R80 R82 R83 R85 R86 R91 R92 R93 R99 R100 R101 R102 R103 R105 R110 R150 R151 R154 R155 R158 R159 R168 R169 R170 R171 R172 R173: "RES, 0, 5%, 0.1 W, 0603"
R7 R46 R47 R52 R53 R55 R56 R58 R59: "RES, 22, 5%, 0.1 W, 0603"
R8 R139 R140 R141 R142 R143 R144: "RES, 50, 1%, 0.1 W, 0603"
R11 R13 R17 R18 R19 R21 R25 R27 R31 R33 R37 R39: "RES, 12.0, 1%, 0.25 W, 1206"
R12 R20 R26 R32 R38 R96 R112: "RES, 10 k, 5%, 0.1 W, 0603"
R41 R42 R43: "RES, 1.00, 1%, 0.25 W, 1206"
R45 R48 R49 R50 R51 R54 R57: library part ERJ-8ENF3573V, "RES, 100 k, 5%, 0.75 W, 1206"
R71 R94: "RES, 16.5, 1%, 0.25 W, 1206"
R81: "RES, 12.1 k, 1%, 0.1 W, 0603"
R90 R107 R109: "RES, 1.00 k, 1%, 0.1 W, 0603"
R98 R108 R122 R125 R127 R128 R129: "RES, 820 k, 1%, 0.25 W, 1206"
R106: "RES, 160 k, 1%, 0.1 W, 0603"
R118 R120: library part PU5931FKHPA0U2L, "RES, 0.004, 1%, 7 W, AEC-Q200 Grade 0, 15x7.75mm"
R162 R163 R164 R165 R166 R167: "RES, 10.0 k, 1%, 0.1 W, 0603"
TP1 TP2 TP3 TP4 TP5 TP6 TP7 TP10 TP11 TP15 TP29 TP31 TP32 TP36 TP37: "Test Point, Miniature, Red, TH"
TP12 TP13 TP14 TP16 TP17 TP18 TP19 TP20 TP21 TP22 TP23 TP24 TP25 TP26 TP27 TP28 TP30 TP33 TP34 TP35: "TEST POINT.  No entry in BOM."
U1 U2 U5 U6 U7 U8 U10: "Isolated Gate Drivers With High CMTI and Scalable Drive Strength, D0008B (SOIC-8)"
U3: library part TLV1117-33CDRJR, "LDO with 4.7 to 15 V Input and 3.3 V Output, -40 to 125 degC, 8-Pin SON (DRJ), Green (RoHS & no Sb/Br)"
U4: "SINGLE SCHMITT-TRIGGER BUFFER, DCK0005A (SOT-5)"
U9: library part LPV521MG, "Nanopower 400nA, 1.8V, R-R I/O CMOS Op Amp, DCK0005A"
U12 U13 U14 U15: library part AMC1306M05DWVR, "Small, High-Precision, Reinforced Isolated Delta-Sigma Modulator with Manchester Coded Output, DWV0008A"
U20 U22: "100 mA, Quasi Low-Dropout Linear Voltage Regulator, 3-pin SOT-23, Pb-Free"
U23: "Single Output LDO, 150 mA, Fixed 3.3 V Output, 2.5 to 24 V Input, with Ultra-Low IQ, 5-pin SOT-23 (DBV), -40 to 125 degC, Green (RoHS & no Sb/Br)"
U24: "IGBT Module,High Power Switching Use Insulated Type, TH"
XF1 XF2: "Fuse Holder, 5AG, TH"
ZZ1: library part AssemblyNoteLabel
ZZ2 ZZ3 ZZ4: library part AssemblyNote

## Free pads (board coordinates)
  round 393.7 hole 393.7 unplated mask+5: 1(2917.64,84.41) 1(2917.64,4415.12) 1(4886.14,84.41) 1(4886.14,4415.12)
  round 236.22 hole 236.22 unplated mask+5: 3(5078.01,5686) 3(5085.05,5039)

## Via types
v1: diameter 32, hole 16, Top Layer to Bottom Layer, 181 vias
v2: diameter 19.68, hole 7.87, Top Layer to Bottom Layer, 5 vias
